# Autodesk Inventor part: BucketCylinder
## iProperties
Author: vincent molino
Shininess: 41.0
Angle Display Precision: 2
Document Length Units: 11272
Document Angle Units: 11286
Document Time Units: 11279
Document Mass Units: 11290
Document Length Units Precision: 3
Document Angle Units Precision: 2
Compacted: True
PropertySet Name: _Private Model Information
Created: 2002-01
Part Number: BucketCylinder
Document SubType Name: Modeling
Designer: vincent molino
Control State: 0
Master: False
Checked Out: False
PropertySet Name: Design Tracking Control
Density: 0.0
Volumn: 0.0
Area: 0.0
PropertySet Name: Model Information
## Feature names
1. Extrusion1
2. Extrusion2
